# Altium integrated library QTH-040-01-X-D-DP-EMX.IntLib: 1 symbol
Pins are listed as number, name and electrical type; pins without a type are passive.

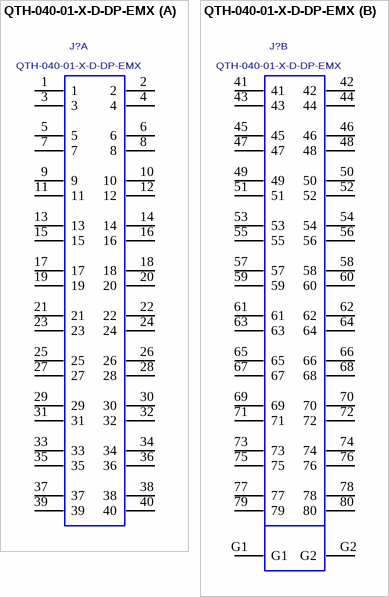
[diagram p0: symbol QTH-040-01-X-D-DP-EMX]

## QTH-040-01-X-D-DP-EMX
designator J?
HIGH SPEEDTERMINAL, 0.5mm PITCH, DIFFERENTIAL PAIRS ,EDGE MOUNT, 80PINS; MANUFACTURER: SAMTEC, INC
footprint QTH-040-01-X-D-DP-EMX
part A pins: 1, 2, 3, 4, 5, 6, 7, 8, 9, 10, 11, 12, 13, 14, 15, 16, 17, 18, 19, 20, 21, 22, 23, 24, 25, 26, 27, 28, 29, 30, 31, 32, 33, 34, 35, 36, 37, 38, 39, 40
part B pins: 41, 42, 43, 44, 45, 46, 47, 48, 49, 50, 51, 52, 53, 54, 55, 56, 57, 58, 59, 60, 61, 62, 63, 64, 65, 66, 67, 68, 69, 70, 71, 72, 73, 74, 75, 76, 77, 78, 79, 80, G1, G2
